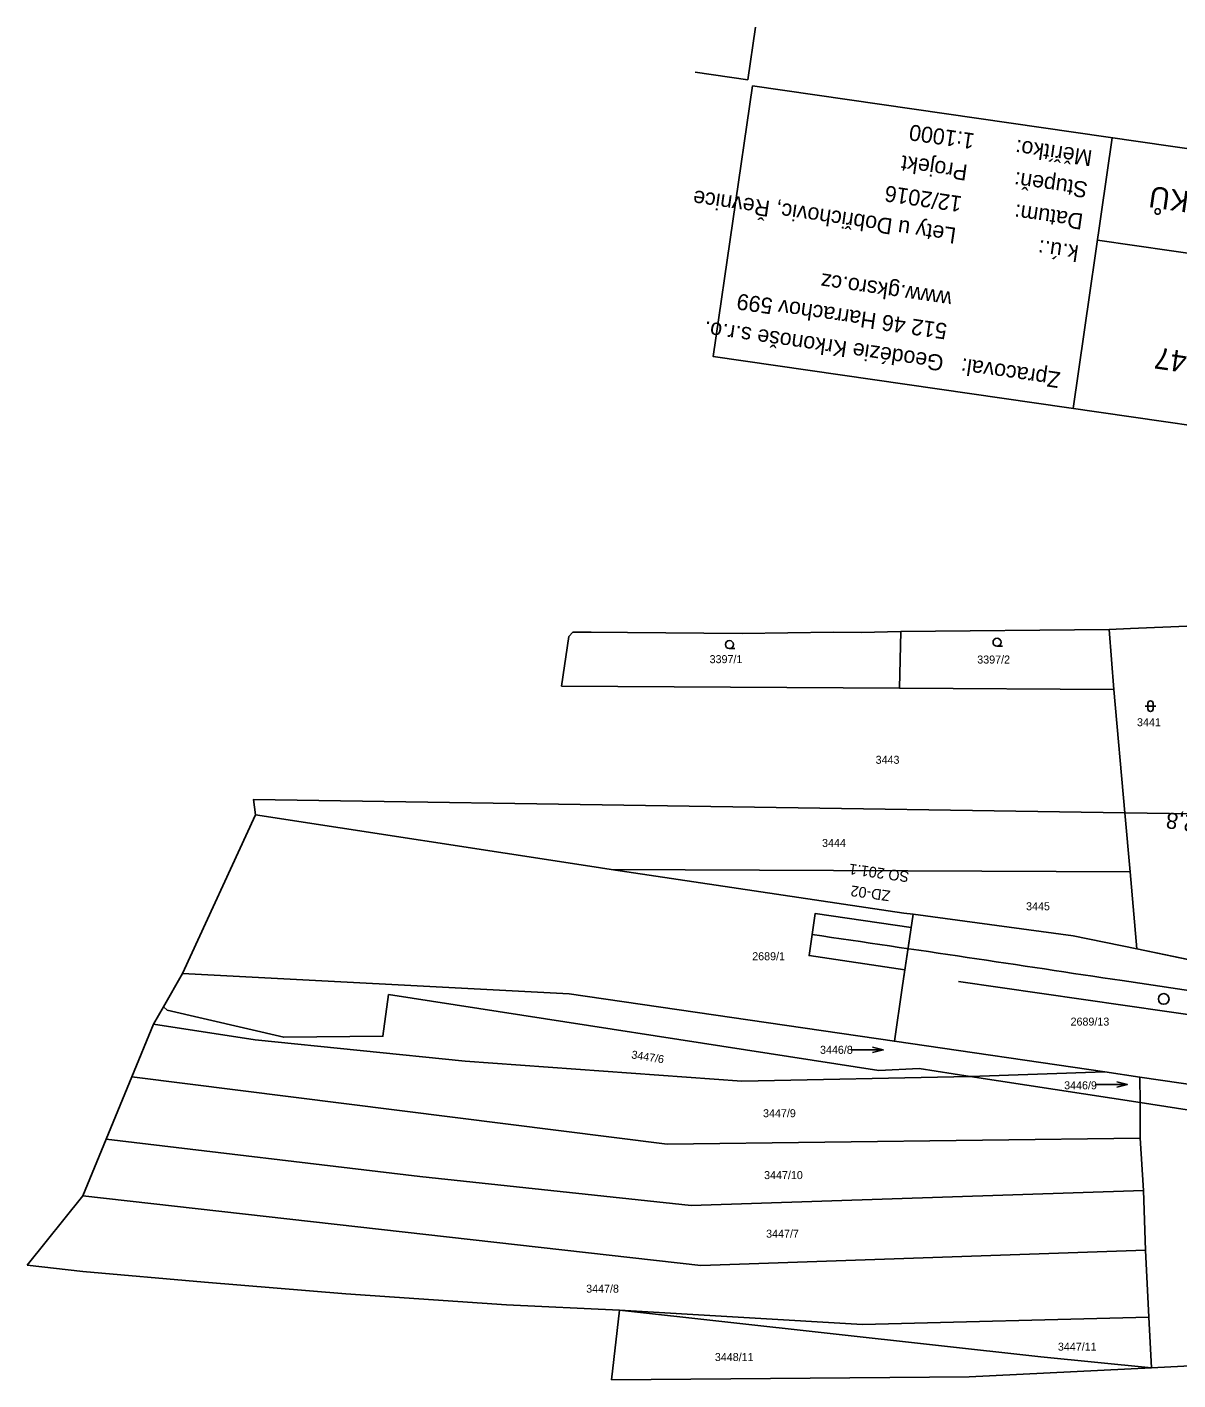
# Model space of a CAD drawing. Extents: x -757895 to -757311, y -1060303 to -1059942.
# Drawn here: x -757895.1 to -757679.5, y -1060195.2 to -1059941.6 of the extents above; entities that cross this region are included whole.
import ezdxf

# ---------------------------------------------------------------- set-up
doc = ezdxf.new("R2010")
doc.units = 0
for name, color, linetype in [('_hektaky', 7, 'Continuous'), ('_SO 102 hektometry', 7, 'Continuous'), ('Dočasné zábory', 7, 'Continuous'), ('Dočasné zábory - čísla', 7, 'Continuous'), ('Legenda 1', 7, 'Continuous'), ('Pozemky SŽDC', 7, 'Continuous'), ('Pozemky ČD', 7, 'Continuous'), ('Vrstva 1', 7, 'Continuous'), ('Vrstva 53', 7, 'Continuous'), ('Vrstva 55', 7, 'Continuous'), ('Vrstva 57', 7, 'Continuous'), ('Vrstva 58', 7, 'Continuous')]:
    doc.layers.add(name, color=color, linetype=linetype)

msp = doc.modelspace()

# ---------------------------------------------------------------- linework, layer by layer
at = {"layer": '_SO 102 hektometry'}
msp.add_circle((-757682.17, -1060123.76), 1, dxfattribs=at)
at = {"layer": 'Dočasné zábory'}
msp.add_lwpolyline([(-757730.65, -1060118.28), (-757729.8, -1060112.49), (-757729.49, -1060110.36), (-757747.46, -1060107.72), (-757748.62, -1060115.63)], close=True, dxfattribs=at)
at = {"layer": 'Legenda 1'}
for p, q in [((-757758.65, -1059941.6), (-757760.08, -1059951.5)), ((-757769.98, -1059950.07), (-757760.08, -1059951.5)), ((-757691.8, -1059962.36), (-757699.12, -1060013.09)), ((-757694.57, -1059981.56), (-757587.21, -1059997.05))]:
    msp.add_line(p, q, dxfattribs=at)
msp.add_lwpolyline([(-757759.23, -1059952.63), (-757584.43, -1059977.86), (-757591.76, -1060028.59), (-757766.56, -1060003.36)], close=True, dxfattribs=at)
at = {"layer": 'Pozemky SŽDC'}
msp.add_lwpolyline([(-757639.93, -1060124.17), (-757687.19, -1060114.38), (-757699.16, -1060111.9), (-757729.12, -1060107.89), (-757729.8, -1060112.49), (-757731.15, -1060121.69), (-757732.62, -1060131.67), (-757693.18, -1060137.43), (-757686.64, -1060138.39), (-757635.44, -1060145.86)], dxfattribs=at)
at = {"layer": 'Pozemky ČD'}
msp.add_lwpolyline([(-757793.56, -1060122.78), (-757732.62, -1060131.67), (-757731.15, -1060121.69), (-757730.65, -1060118.28), (-757748.62, -1060115.63), (-757747.46, -1060107.72), (-757729.49, -1060110.36), (-757729.12, -1060107.89), (-757730.83, -1060107.66), (-757785.7, -1060099.48), (-757789.66, -1060098.89), (-757852.31, -1060089.26), (-757866, -1060118.97)], close=True, dxfattribs=at)
at = {"layer": 'Vrstva 1'}
for p, q in [((-757429.32, -1060162.53), (-757720.62, -1060120.47)), ((-757665.26, -1060124.05), (-757689.98, -1060120.32))]:
    msp.add_line(p, q, dxfattribs=at)
msp.add_arc((-759559.14, -1072479.78), 12500, 81.400126, 81.669213, dxfattribs=at)
at = {"layer": 'Vrstva 53'}
for points in [[(-757852.31, -1060089.26), (-757789.66, -1060098.89), (-757785.7, -1060099.48), (-757730.83, -1060107.66), (-757729.12, -1060107.89), (-757699.16, -1060111.9), (-757687.19, -1060114.38), (-757639.93, -1060124.17)], [(-757328.56, -1060183.46), (-757338.29, -1060184.85), (-757361.91, -1060181.63), (-757443.58, -1060171.99), (-757470.38, -1060167.04), (-757513.1, -1060164.5), (-757526.21, -1060162.71), (-757533.6, -1060161.43), (-757535.01, -1060161.18), (-757542.9, -1060160.49), (-757543.88, -1060160.4), (-757632.1, -1060146.3), (-757634.26, -1060145.96), (-757635.44, -1060145.86), (-757686.64, -1060138.39), (-757693.18, -1060137.43), (-757732.62, -1060131.67), (-757793.56, -1060122.78), (-757866, -1060118.97)]]:
    msp.add_lwpolyline(points, dxfattribs=at)
at = {"layer": 'Vrstva 55'}
for p, q in [((-757688.39, -1060054.34), (-757677.84, -1060053.89)), ((-757794.99, -1060065.12), (-757793.62, -1060055.81)), ((-757761.16, -1060055.23), (-757782.62, -1060055.08)), ((-757731.45, -1060054.87), (-757738.86, -1060055.09)), ((-757731.69, -1060065.52), (-757731.45, -1060054.87)), ((-757692.38, -1060054.51), (-757731.45, -1060054.87)), ((-757692.38, -1060054.51), (-757688.39, -1060054.34)), ((-757691.5, -1060065.78), (-757692.38, -1060054.51)), ((-757794.99, -1060065.12), (-757731.69, -1060065.52)), ((-757731.69, -1060065.52), (-757691.5, -1060065.78)), ((-757691.5, -1060065.78), (-757689.45, -1060088.87)), ((-757689.45, -1060088.87), (-757688.47, -1060099.93)), ((-757689.45, -1060088.87), (-757676.88, -1060089.06)), ((-757785.7, -1060099.48), (-757688.47, -1060099.93)), ((-757688.47, -1060099.93), (-757687.19, -1060114.38)), ((-757687.19, -1060114.38), (-757639.93, -1060124.17)), ((-757869.56, -1060125.23), (-757866, -1060118.97)), ((-757866, -1060118.97), (-757793.56, -1060122.78)), ((-757793.56, -1060122.78), (-757732.62, -1060131.67)), ((-757871.42, -1060128.49), (-757869.56, -1060125.23)), ((-757875.47, -1060138.34), (-757871.42, -1060128.49)), ((-757693.18, -1060137.43), (-757732.62, -1060131.67)), ((-757718.41, -1060138.26), (-757693.18, -1060137.43)), ((-757686.64, -1060138.39), (-757693.18, -1060137.43)), ((-757880.28, -1060150.04), (-757875.47, -1060138.34)), ((-757718.41, -1060138.26), (-757686.61, -1060143.18)), ((-757686.61, -1060143.18), (-757686.64, -1060138.39)), ((-757686.57, -1060149.86), (-757686.61, -1060143.18)), ((-757884.65, -1060160.67), (-757880.28, -1060150.04)), ((-757685.97, -1060159.64), (-757686.57, -1060149.86)), ((-757685.61, -1060170.82), (-757685.97, -1060159.64)), ((-757895.12, -1060173.65), (-757884.65, -1060160.67)), ((-757684.97, -1060183.38), (-757685.61, -1060170.82)), ((-757884.69, -1060174.86), (-757895.12, -1060173.65)), ((-757861.86, -1060176.83), (-757884.69, -1060174.86)), ((-757835.37, -1060179.05), (-757861.86, -1060176.83)), ((-757805.28, -1060181.09), (-757835.37, -1060179.05)), ((-757784.15, -1060182.07), (-757805.28, -1060181.09)), ((-757785.65, -1060195.16), (-757784.15, -1060182.07)), ((-757684.44, -1060192.89), (-757684.97, -1060183.38))]:
    msp.add_line(p, q, dxfattribs=at)
for points in [[(-757782.62, -1060055.08), (-757789.45, -1060055.02), (-757792.84, -1060054.99), (-757793.62, -1060055.81)], [(-757738.86, -1060055.09), (-757744.02, -1060055.04), (-757761.16, -1060055.23)], [(-757852.31, -1060089.26), (-757852.72, -1060086.39), (-757689.45, -1060088.87)], [(-757785.7, -1060099.48), (-757789.66, -1060098.89), (-757852.31, -1060089.26)], [(-757729.12, -1060107.89), (-757730.83, -1060107.66), (-757785.7, -1060099.48)], [(-757732.62, -1060131.67), (-757731.15, -1060121.69), (-757729.8, -1060112.49), (-757729.12, -1060107.89)], [(-757729.12, -1060107.89), (-757699.16, -1060111.9), (-757687.19, -1060114.38)], [(-757869.56, -1060125.23), (-757868.9, -1060125.84), (-757847.02, -1060130.94), (-757828.46, -1060130.73), (-757827.38, -1060122.93), (-757735.56, -1060137.19), (-757727.96, -1060136.79), (-757718.41, -1060138.26)], [(-757871.42, -1060128.49), (-757852.4, -1060131.41), (-757813.07, -1060135.44), (-757761.18, -1060139.17), (-757718.41, -1060138.26)], [(-757875.47, -1060138.34), (-757775.17, -1060150.97), (-757686.57, -1060149.86)], [(-757634.26, -1060145.96), (-757635.44, -1060145.86), (-757686.64, -1060138.39)], [(-757686.61, -1060143.18), (-757664.14, -1060146.65), (-757658.56, -1060153.53), (-757630.94, -1060158.73)], [(-757685.97, -1060159.64), (-757770.72, -1060162.45), (-757821.53, -1060157.03), (-757880.28, -1060150.04)], [(-757884.65, -1060160.67), (-757768.87, -1060173.68), (-757685.61, -1060170.82)], [(-757784.15, -1060182.07), (-757738.63, -1060184.76), (-757684.97, -1060183.38)], [(-757784.15, -1060182.07), (-757705.21, -1060190.84), (-757684.44, -1060192.89)], [(-757785.65, -1060195.16), (-757718.62, -1060194.56), (-757684.44, -1060192.89)], [(-757684.44, -1060192.89), (-757656.46, -1060191.47), (-757636.9, -1060190.98)]]:
    msp.add_lwpolyline(points, dxfattribs=at)
at = {"layer": 'Vrstva 58'}
for p, q in [((-757763.52, -1060058.08), (-757762.52, -1060058.08)), ((-757713.4, -1060057.66), (-757712.4, -1060057.66)), ((-757685.65, -1060068.88), (-757683.65, -1060068.88)), ((-757685.15, -1060068.38), (-757685.15, -1060069.38)), ((-757684.15, -1060068.38), (-757684.15, -1060069.38)), ((-757740.7, -1060133.31), (-757734.7, -1060133.31)), ((-757694.98, -1060139.78), (-757688.98, -1060139.78))]:
    msp.add_line(p, q, dxfattribs=at)
for points in [[(-757736.7, -1060132.81), (-757734.7, -1060133.31), (-757736.7, -1060133.81)], [(-757690.98, -1060139.28), (-757688.98, -1060139.78), (-757690.98, -1060140.28)]]:
    msp.add_lwpolyline(points, dxfattribs=at)
for centre in [(-757713.4, -1060056.91), (-757763.52, -1060057.33)]:
    msp.add_circle(centre, 0.75, dxfattribs=at)
for centre, start, end in [((-757684.65, -1060068.38), 0, 180), ((-757684.65, -1060069.38), 180, 0)]:
    msp.add_arc(centre, 0.5, start, end, dxfattribs=at)

# ---------------------------------------------------------------- texts
at = {"layer": '_hektaky'}
msp.add_text('22,8', height=3, rotation=171.4001, dxfattribs=at).set_placement((-757673.76, -1060089.9))
at = {"layer": 'Dočasné zábory - čísla'}
for s, p in [('SO 201.1', (-757729.77, -1060099.92)), ('ZD-02', (-757733.3, -1060103.48))]:
    msp.add_text(s, height=2, rotation=172.2261, dxfattribs=at).set_placement(p)
at = {"layer": 'Legenda 1'}
for s, p in [('Měřítko:       1:1000', (-757695.4, -1059964.75)), ('Stupeň:        Projekt', (-757696.26, -1059970.69)), ('k.ú.:              Lety u Dobřichovic, Řevnice', (-757697.97, -1059982.57)), ('Datum:         12/2016', (-757697.11, -1059976.63)), ('                    www.gksro.cz', (-757699.68, -1059994.45)), ('                    512 46 Harrachov 599', (-757700.54, -1060000.38)), ('Zpracoval:   Geodézie Krkonoše s.r.o.', (-757701.4, -1060006.32))]:
    msp.add_text(s, height=3, rotation=171.7882, dxfattribs=at).set_placement(p)
at = {"layer": 'Vrstva 55'}
for s, p in [('I.2.2 - SITUACE ZÁBORŮ POZEMKŮ', (-757595.43, -1059984.22)), ('Rekonstrukce mostu v km 22,647', (-757604.96, -1060012.93))]:
    msp.add_text(s, height=4, rotation=171.7882, dxfattribs=at).set_placement(p)
at = {"layer": 'Vrstva 57'}
for s, p in [('3397/1', (-757767.24, -1060060.82)), ('3397/2', (-757717.1, -1060060.89)), ('3441', (-757687.17, -1060072.64)), ('3443', (-757736.14, -1060079.68)), ('3444', (-757746.18, -1060095.27)), ('3445', (-757707.95, -1060107.13)), ('2689/1', (-757759.26, -1060116.5)), ('2689/13', (-757699.62, -1060128.75)), ('3446/8', (-757746.56, -1060134.04)), ('3446/9', (-757700.82, -1060140.69)), ('3447/9', (-757757.23, -1060145.92)), ('3447/10', (-757757.04, -1060157.52)), ('3447/7', (-757756.66, -1060168.5)), ('3447/8', (-757790.37, -1060178.8)), ('3447/11', (-757701.99, -1060189.67)), ('3448/11', (-757766.26, -1060191.62))]:
    msp.add_text(s, height=1.5, dxfattribs=at).set_placement(p)
msp.add_text('3447/6', height=1.5, rotation=351, dxfattribs=at).set_placement((-757781.98, -1060134.88))

doc.saveas('drawing.dxf')
